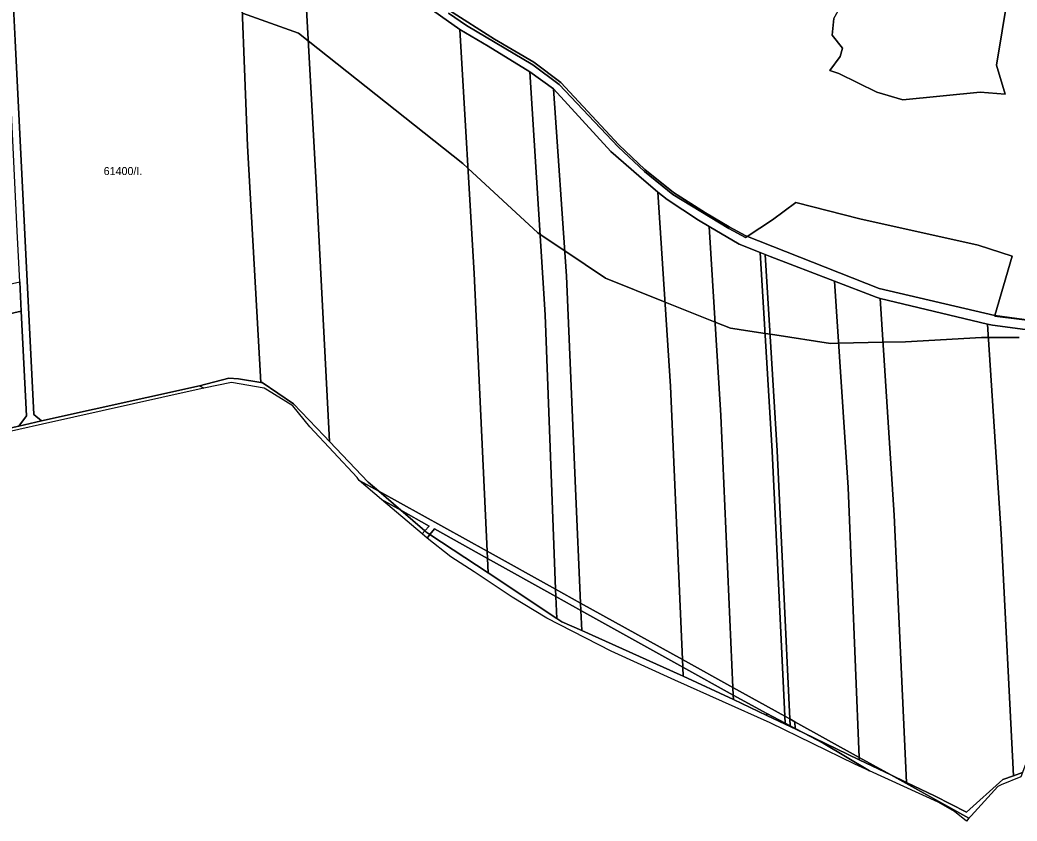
# Model space of a CAD drawing. Extents: x -522079 to -518833, y -1142400 to -1139961.
# Drawn here: x -520002 to -519379, y -1141872 to -1141371 of the extents above; entities that cross this region are included whole.
import ezdxf

# ---------------------------------------------------------------- set-up
doc = ezdxf.new("R2010")
doc.units = 0
for name, color, linetype in [('95560013', 7, 'Continuous'), ('95620013', 7, 'Continuous'), ('95640013', 7, 'Continuous'), ('95660013', 7, 'Continuous')]:
    doc.layers.add(name, color=color, linetype=linetype)

msp = doc.modelspace()

# ---------------------------------------------------------------- linework, layer by layer
at = {"layer": '95560013'}
for points in [[(-519988.83, -1141621.62), (-519993.67, -1141617.6), (-520005.29, -1141383.92), (-520010.89, -1141271.2), (-520005.98, -1141266.96), (-519865.42, -1141315.8), (-519860.18, -1141449.65), (-519851.95, -1141597.5), (-519865.85, -1141595.23), (-519871.86, -1141594.87), (-519890.16, -1141599.67)], [(-519865.42, -1141315.8), (-519825.24, -1141330.38), (-519817.29, -1141473.31), (-519808.88, -1141634.44), (-519812.26, -1141630.88), (-519831.57, -1141610.83), (-519850.96, -1141597.66), (-519851.95, -1141597.5), (-519860.18, -1141449.65)], [(-519825.24, -1141330.38), (-519793.08, -1141341.43), (-519751.63, -1141360.04), (-519727.64, -1141376.95), (-519718.52, -1141529.55), (-519710.49, -1141703.04), (-519778.21, -1141665.51), (-519784.86, -1141659.77), (-519808.88, -1141634.44), (-519817.29, -1141473.31)], [(-519710.49, -1141703.04), (-519718.52, -1141529.55), (-519727.64, -1141376.95), (-519709.78, -1141387.41), (-519683.78, -1141403.39), (-519674.25, -1141555.28), (-519667.71, -1141726.74)], [(-519683.78, -1141403.39), (-519668.96, -1141414.21), (-519660.95, -1141531.22), (-519655.21, -1141663.8), (-519652.11, -1141735.39), (-519667.71, -1141726.74), (-519674.25, -1141555.28)], [(-519660.95, -1141531.22), (-519668.96, -1141414.21), (-519633.24, -1141453.23), (-519615.77, -1141468.45), (-519603.81, -1141478.65), (-519595.83, -1141599.95), (-519588.39, -1141770.7), (-519652.11, -1141735.39), (-519655.21, -1141663.8)], [(-519564.39, -1141618.27), (-519556.98, -1141788.11), (-519588.39, -1141770.7), (-519595.83, -1141599.95), (-519603.81, -1141478.65), (-519598.08, -1141483.22), (-519578.53, -1141496.09), (-519571.87, -1141500.11)], [(-519564.39, -1141618.27), (-519571.87, -1141500.11), (-519553.06, -1141511.15), (-519539.97, -1141516.35), (-519532.32, -1141640.4), (-519524.56, -1141806.07), (-519556.98, -1141788.11)], [(-519539.97, -1141516.35), (-519536.79, -1141517.61), (-519529.23, -1141640.2), (-519521.37, -1141807.84), (-519524.56, -1141806.07), (-519532.32, -1141640.4)], [(-519518.28, -1141809.56), (-519521.37, -1141807.84), (-519529.23, -1141640.2), (-519536.79, -1141517.61), (-519533.7, -1141518.85), (-519493.41, -1141534.2), (-519484.95, -1141663.16), (-519478.03, -1141831.87)], [(-520141.93, -1141565.64), (-520002.49, -1141534.74), (-520001.59, -1141552.99), (-520274.84, -1141614.95), (-520276.82, -1141595.78)], [(-519464.89, -1141545.09), (-519456.22, -1141680.46), (-519448.38, -1141847.58), (-519458.26, -1141842.83), (-519478.03, -1141831.87), (-519484.95, -1141663.16), (-519493.41, -1141534.2), (-519467.42, -1141544.19)], [(-519381.7, -1141843.28), (-519388.28, -1141845.72), (-519410.94, -1141866.01), (-519430.66, -1141856.11), (-519448.38, -1141847.58), (-519456.22, -1141680.46), (-519464.89, -1141545.09), (-519397.82, -1141561.07), (-519389.39, -1141692.08)], [(-520001.59, -1141552.99), (-519998.35, -1141618.37), (-520003.08, -1141624.98), (-520133.69, -1141653.91), (-520266.52, -1141683.24), (-520268.73, -1141674.23), (-520274.84, -1141614.95)], [(-519338.11, -1141700.9), (-519336.47, -1141734.52), (-519376.07, -1141841.19), (-519381.7, -1141843.28), (-519389.39, -1141692.08), (-519397.82, -1141561.07), (-519394.67, -1141561.74), (-519364.95, -1141565.79), (-519349.35, -1141570.28), (-519346.66, -1141571.83)], [(-519871.86, -1141594.87), (-519865.85, -1141595.23), (-519851.95, -1141597.5), (-519850.96, -1141597.66), (-519831.57, -1141610.83), (-519812.26, -1141630.88), (-519808.88, -1141634.44), (-519784.86, -1141659.77), (-519778.21, -1141665.51), (-519790.37, -1141658.77), (-519791.74, -1141656.89), (-519821.3, -1141625.26), (-519831.88, -1141612.23), (-519847.75, -1141602.33), (-519849.83, -1141601.06), (-519870.13, -1141597.7), (-519887.54, -1141601.15), (-519890.16, -1141599.67)], [(-519776.39, -1141670.73), (-519764.48, -1141677.36), (-519749.42, -1141690.34), (-519751.14, -1141692.22)], [(-519764.48, -1141677.36), (-519746.63, -1141687.29), (-519749.42, -1141690.34)], [(-519718.63, -1141715.98), (-519733.23, -1141706.57), (-519747.91, -1141694.83), (-519746.19, -1141692.62), (-519709.93, -1141716.59), (-519667.02, -1141744.96), (-519663.82, -1141747.08), (-519651.37, -1141752.53), (-519589.8, -1141780.27), (-519588.09, -1141781.01), (-519556.64, -1141795.77), (-519535.66, -1141805.67), (-519524.32, -1141811.02), (-519521.15, -1141812.55), (-519512.87, -1141816.53), (-519500.53, -1141823.01), (-519471.59, -1141840.28), (-519480.84, -1141836.08), (-519533.59, -1141810.27), (-519593.13, -1141783.65), (-519633.06, -1141765.56), (-519673.22, -1141744.78), (-519694.8, -1141731.79)], [(-519710.31, -1141707.49), (-519709.93, -1141716.59), (-519746.19, -1141692.62), (-519743.43, -1141689.07)], [(-519667.54, -1141731.28), (-519667.02, -1141744.96), (-519709.93, -1141716.59), (-519710.31, -1141707.49)], [(-519667.54, -1141731.28), (-519651.91, -1141739.97), (-519651.37, -1141752.53), (-519663.82, -1141747.08), (-519667.02, -1141744.96)], [(-519588.18, -1141775.42), (-519588.09, -1141781.01), (-519589.8, -1141780.27), (-519651.37, -1141752.53), (-519651.91, -1141739.97)], [(-519556.64, -1141795.77), (-519588.09, -1141781.01), (-519588.18, -1141775.42), (-519556.77, -1141792.9)], [(-519556.64, -1141795.77), (-519556.77, -1141792.9), (-519535.73, -1141804.33), (-519535.66, -1141805.67)], [(-519535.73, -1141804.33), (-519524.35, -1141810.51), (-519524.32, -1141811.02), (-519535.66, -1141805.67)], [(-519521.15, -1141812.55), (-519524.32, -1141811.02), (-519524.35, -1141810.51), (-519521.17, -1141812.18)], [(-519512.87, -1141816.53), (-519521.15, -1141812.55), (-519521.17, -1141812.18), (-519518.08, -1141813.8)], [(-519389.29, -1141849.01), (-519391.5, -1141849.93), (-519408.1, -1141868.36), (-519409.46, -1141869.87), (-519458.26, -1141842.83), (-519448.38, -1141847.58), (-519430.66, -1141856.11), (-519410.94, -1141866.01), (-519388.28, -1141845.72), (-519381.7, -1141843.28), (-519376.07, -1141841.19), (-519377.1, -1141843.96)]]:
    msp.add_lwpolyline(points, close=True, dxfattribs=at)
at = {"layer": '95620013'}
msp.add_lwpolyline([(-519494.92, -1141380.6), (-519493.9, -1141370.24), (-519484.66, -1141353.81), (-519477.91, -1141348.96), (-519470.8, -1141337.38), (-519465.42, -1141322.27), (-519385.2, -1141356.16), (-519392.16, -1141399.31), (-519386.73, -1141417.35), (-519402.53, -1141416.1), (-519450.75, -1141420.94), (-519466.91, -1141416.21), (-519490.7, -1141404.57), (-519496.45, -1141402.69), (-519489.99, -1141393.96), (-519488.36, -1141388.76)], close=True, dxfattribs=at)
for points in [[(-519493.9, -1141370.24), (-519494.92, -1141380.6), (-519488.36, -1141388.76), (-519489.99, -1141393.96), (-519496.45, -1141402.69), (-519490.7, -1141404.57), (-519466.91, -1141416.21), (-519450.75, -1141420.94), (-519402.53, -1141416.1), (-519386.73, -1141417.35), (-519392.16, -1141399.31), (-519385.2, -1141356.16)], [(-519362.75, -1141559.82), (-519393.2, -1141555.81), (-519465.6, -1141538.79), (-519548.85, -1141506.03), (-519559.27, -1141500.34), (-519574.1, -1141491.51), (-519594.12, -1141478.91), (-519611.87, -1141464.55), (-519628.16, -1141449.15), (-519664.49, -1141410.15), (-519681.23, -1141397.53), (-519705.92, -1141383), (-519733.94, -1141365.09)]]:
    msp.add_lwpolyline(points, dxfattribs=at)
at = {"layer": '95640013'}
for points in [[(-519998.35, -1141618.37), (-520001.59, -1141552.99), (-520002.49, -1141534.74), (-520004.05, -1141503.1), (-520007.71, -1141429.14), (-520010.91, -1141364.55), (-520011.78, -1141349.43), (-520013.01, -1141327.96), (-520014.41, -1141303.65), (-520015.8, -1141279.3), (-520015.63, -1141269.2), (-520020.82, -1141261.97), (-520005.98, -1141266.96), (-520010.89, -1141271.2), (-520005.29, -1141383.92), (-519993.67, -1141617.6), (-519988.83, -1141621.62), (-520003.08, -1141624.98)], [(-520266.52, -1141683.24), (-520133.69, -1141653.91), (-520003.08, -1141624.98), (-519988.83, -1141621.62), (-519890.16, -1141599.67), (-519887.54, -1141601.15), (-519894.12, -1141602.61), (-519988.36, -1141623.57), (-520003.05, -1141627.05), (-520133.25, -1141655.87), (-520266.08, -1141685.14)], [(-519790.37, -1141658.77), (-519778.21, -1141665.51), (-519764.48, -1141677.36), (-519776.39, -1141670.73)], [(-519778.21, -1141665.51), (-519710.49, -1141703.04), (-519710.31, -1141707.49), (-519743.43, -1141689.07), (-519746.19, -1141692.62), (-519748.73, -1141690.94), (-519749.42, -1141690.34), (-519746.63, -1141687.29), (-519764.48, -1141677.36)], [(-519746.19, -1141692.62), (-519747.91, -1141694.83), (-519751.14, -1141692.22), (-519749.42, -1141690.34), (-519748.73, -1141690.94)], [(-519710.49, -1141703.04), (-519667.71, -1141726.74), (-519667.54, -1141731.28), (-519710.31, -1141707.49)], [(-519667.54, -1141731.28), (-519667.71, -1141726.74), (-519652.11, -1141735.39), (-519651.91, -1141739.97)], [(-519588.39, -1141770.7), (-519588.18, -1141775.42), (-519651.91, -1141739.97), (-519652.11, -1141735.39)], [(-519556.77, -1141792.9), (-519588.18, -1141775.42), (-519588.39, -1141770.7), (-519556.98, -1141788.11)], [(-519556.77, -1141792.9), (-519556.98, -1141788.11), (-519524.56, -1141806.07), (-519524.35, -1141810.51), (-519535.73, -1141804.33)], [(-519524.35, -1141810.51), (-519524.56, -1141806.07), (-519521.37, -1141807.84), (-519521.17, -1141812.18)], [(-519521.17, -1141812.18), (-519521.37, -1141807.84), (-519518.28, -1141809.56), (-519518.08, -1141813.8)], [(-519477.97, -1141833.34), (-519512.87, -1141816.53), (-519518.08, -1141813.8), (-519518.28, -1141809.56), (-519478.03, -1141831.87)], [(-519477.97, -1141833.34), (-519458.26, -1141842.83), (-519409.46, -1141869.87), (-519411.05, -1141871.62), (-519418.41, -1141865.69), (-519428.71, -1141859.77), (-519471.59, -1141840.28), (-519500.53, -1141823.01), (-519512.87, -1141816.53)], [(-519478.03, -1141831.87), (-519458.26, -1141842.83), (-519477.97, -1141833.34)]]:
    msp.add_lwpolyline(points, close=True, dxfattribs=at)
for points in [[(-519364.95, -1141565.79), (-519394.67, -1141561.74), (-519397.82, -1141561.07), (-519464.89, -1141545.09), (-519467.42, -1141544.19), (-519493.41, -1141534.2), (-519533.7, -1141518.85), (-519536.79, -1141517.61), (-519539.97, -1141516.35), (-519553.06, -1141511.15), (-519571.87, -1141500.11), (-519578.53, -1141496.09), (-519598.08, -1141483.22), (-519603.81, -1141478.65), (-519615.77, -1141468.45), (-519633.24, -1141453.23), (-519668.96, -1141414.21), (-519683.78, -1141403.39), (-519709.78, -1141387.41), (-519727.64, -1141376.95), (-519751.63, -1141360.04)], [(-519733.94, -1141365.09), (-519705.92, -1141383), (-519681.23, -1141397.53), (-519664.49, -1141410.15), (-519628.16, -1141449.15), (-519611.87, -1141464.55), (-519594.12, -1141478.91), (-519574.1, -1141491.51), (-519559.27, -1141500.34), (-519548.85, -1141506.03), (-519465.6, -1141538.79), (-519393.2, -1141555.81), (-519362.75, -1141559.82)]]:
    msp.add_lwpolyline(points, dxfattribs=at)
at = {"layer": '95660013'}
for points in [[(-519863.42, -1141366.88), (-519828.32, -1141379.25), (-519822.25, -1141384.07), (-519725.68, -1141460.78), (-519722.45, -1141463.77), (-519678.79, -1141504.16), (-519677.4, -1141505.09), (-519662.03, -1141515.37), (-519636.59, -1141532.38), (-519599.29, -1141547.35), (-519568.09, -1141559.87), (-519558.44, -1141563.74), (-519556.95, -1141563.96), (-519549.16, -1141565.14), (-519536.85, -1141566.99), (-519536.62, -1141567.02), (-519533.71, -1141567.46), (-519530.67, -1141567.92), (-519495.92, -1141573.15), (-519490.86, -1141573.03), (-519463.14, -1141572.42), (-519449.03, -1141572.1), (-519401.62, -1141569.49), (-519397.28, -1141569.49), (-519378.18, -1141569.49)], [(-519378.18, -1141569.49), (-519397.28, -1141569.49), (-519401.62, -1141569.49), (-519449.03, -1141572.1), (-519463.14, -1141572.42), (-519490.86, -1141573.03), (-519495.92, -1141573.15), (-519530.67, -1141567.92), (-519533.71, -1141567.46), (-519536.62, -1141567.02), (-519536.85, -1141566.99), (-519549.16, -1141565.14), (-519556.95, -1141563.96), (-519558.44, -1141563.74), (-519568.09, -1141559.87), (-519599.29, -1141547.35), (-519636.59, -1141532.38), (-519662.03, -1141515.37), (-519677.4, -1141505.09), (-519678.79, -1141504.16), (-519722.45, -1141463.77), (-519725.68, -1141460.78), (-519822.25, -1141384.07), (-519828.32, -1141379.25), (-519863.42, -1141366.88)], [(-519734.68, -1141366.82), (-519723.37, -1141374.45), (-519681.85, -1141399.04), (-519665.4, -1141411.5), (-519628.6, -1141450.42), (-519612.25, -1141465.74), (-519594.44, -1141480.03), (-519559.52, -1141501.31), (-519549.08, -1141506.95), (-519548.11, -1141506.32), (-519532.23, -1141495.98), (-519517.64, -1141485.04), (-519477.67, -1141495.35), (-519403.69, -1141511.76), (-519382.45, -1141518.76), (-519393.21, -1141555.81), (-519393.29, -1141556.08), (-519362.83, -1141559.96)], [(-519362.83, -1141559.96), (-519393.29, -1141556.08), (-519393.21, -1141555.81), (-519382.45, -1141518.76), (-519403.69, -1141511.76), (-519477.67, -1141495.35), (-519517.64, -1141485.04), (-519532.23, -1141495.98), (-519548.11, -1141506.32), (-519549.08, -1141506.95), (-519559.52, -1141501.31), (-519594.44, -1141480.03), (-519612.25, -1141465.74), (-519628.6, -1141450.42), (-519665.4, -1141411.5), (-519681.85, -1141399.04), (-519723.37, -1141374.45), (-519734.68, -1141366.82)], [(-519377.1, -1141843.96), (-519389.29, -1141849.01), (-519391.5, -1141849.93), (-519408.1, -1141868.36), (-519409.46, -1141869.87), (-519411.05, -1141871.62), (-519418.41, -1141865.69), (-519428.71, -1141859.77), (-519471.59, -1141840.28), (-519480.84, -1141836.08), (-519533.59, -1141810.27), (-519593.13, -1141783.65), (-519633.06, -1141765.56), (-519673.22, -1141744.78), (-519694.8, -1141731.79), (-519718.63, -1141715.98), (-519733.23, -1141706.57), (-519747.91, -1141694.83), (-519751.14, -1141692.22), (-519776.39, -1141670.73), (-519790.37, -1141658.77), (-519791.74, -1141656.89), (-519821.3, -1141625.26), (-519831.88, -1141612.23), (-519847.75, -1141602.33), (-519849.83, -1141601.06), (-519870.13, -1141597.7), (-519887.54, -1141601.15), (-519894.12, -1141602.61), (-519988.36, -1141623.57), (-520003.05, -1141627.05)]]:
    msp.add_lwpolyline(points, dxfattribs=at)

# ---------------------------------------------------------------- texts
msp.add_text('61400/I.', height=5, dxfattribs=at).set_placement((-519950.07, -1141467.98))

doc.saveas('drawing.dxf')
